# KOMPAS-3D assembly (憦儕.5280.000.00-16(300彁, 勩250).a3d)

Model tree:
1. Плоскость XY
2. Плоскость ZX
3. Плоскость ZY
4. Ось X
5. Ось Y
6. Ось Z
7. Начало координат  (labels: Операция без истории:1; Операция без истории:2; Операция без истории:3; Операция без истории:4)

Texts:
  Линия-выноска #1
  Линия-выноска #2
  Линия-выноска #3
  Отклонения формы и база
  Марка координационной оси
  Марка/позиционное обозначение с линией-выноской
  Марка/позиционное обозначение на линии
  Марка/позиционное обозначение без линии-выноски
